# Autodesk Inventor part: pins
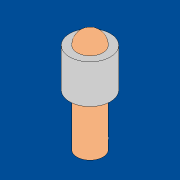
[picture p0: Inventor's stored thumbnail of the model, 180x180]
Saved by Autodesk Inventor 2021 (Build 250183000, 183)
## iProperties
Created: 2020-10
Part Number: pins
Material: Generic
Document SubType Name: Modeling
Designer: Stu
Density: 1 g/cm^3
Appearance: Default
Author: Stu
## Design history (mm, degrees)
sketch "Sketch1"
  geometry: C1 r 3.175 at (0, 0); 1 further point
  constraints: 1 centre point, 1 coincident
  dimensions: "d0" = 6.35 diameter of C1
extrude "Extrusion1" new body sketch "Sketch1" distance "d1" = 25.4; taper "d2" = 0 deg
fillet "Fillet1" dims "d3" = 3.175
workplane "Work Plane1"
sketch "Sketch2"
  geometry: C1 r 3.175 at (0, 0) reference; C2 r 5 at (0, 0); 1 further point
  constraints: 1 centre point, 1 coincident
  dimensions: "d5" = 10 diameter of C2
extrude "Extrusion2" join sketch "Sketch2" distance "d6" = 9.525; taper "d7" = 0 deg
body "Solid1"
other parameters: "d4" = -12.7
